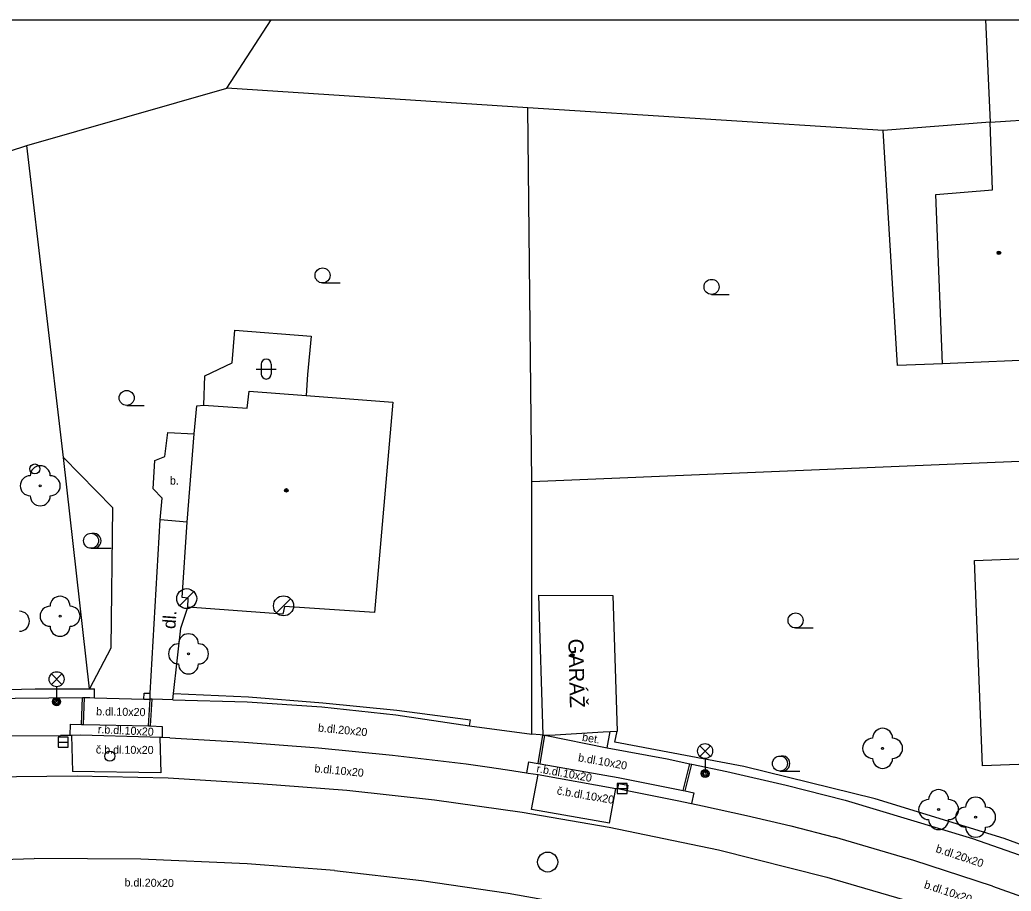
# Model space of a CAD drawing. Extents: x -600309 to -598967, y -1161267 to -1160292.
# Drawn here: x -599777.27 to -599727.72, y -1160335.89 to -1160292.35 of the extents above; entities that cross this region are included whole.
import ezdxf

# ---------------------------------------------------------------- set-up
doc = ezdxf.new("R2010")
doc.units = 0
for name, color, linetype in [('Level 10', 7, 'Continuous'), ('Level 11', 7, 'Continuous'), ('Level 21', 7, 'Continuous'), ('Level 22', 7, 'Continuous'), ('Level 27', 7, 'Continuous'), ('Level 28', 7, 'Continuous'), ('Level 33', 7, 'Continuous'), ('Level 36', 7, 'Continuous'), ('Level 39', 7, 'Continuous'), ('Level 40', 7, 'Continuous'), ('Level 41', 7, 'Continuous'), ('Level 5', 7, 'Continuous'), ('Level 51', 7, 'Continuous'), ('Level 6', 7, 'Continuous'), ('Level 7', 7, 'Continuous'), ('Level 8', 7, 'Continuous'), ('Vrstva 63', 7, 'Continuous')]:
    doc.layers.add(name, color=color, linetype=linetype)

msp = doc.modelspace()

# ---------------------------------------------------------------- linework, layer by layer
at = {"layer": 'Level 10'}
for points in [[(-599783.14, -1160328.38), (-599780.51, -1160328.22), (-599777.87, -1160328.13), (-599775.23, -1160328.11)], [(-599769.77, -1160328.23), (-599770.16, -1160328.21), (-599770.28, -1160328.21), (-599770.75, -1160328.19), (-599774.23, -1160328.1), (-599774.68, -1160328.11), (-599774.77, -1160328.11), (-599775.23, -1160328.11)], [(-599769.77, -1160328.23), (-599766.06, -1160328.44), (-599762.35, -1160328.72), (-599758.65, -1160329.09)], [(-599758.65, -1160329.09), (-599754.96, -1160329.53)], [(-599754.96, -1160329.53), (-599753.92, -1160329.67)], [(-599753.92, -1160329.67), (-599752.89, -1160329.82)], [(-599752.89, -1160329.82), (-599751.95, -1160329.98), (-599751.86, -1160329.99)], [(-599751.86, -1160329.99), (-599751.37, -1160330.06), (-599747.48, -1160330.75), (-599747.39, -1160330.76)], [(-599747.39, -1160330.76), (-599746.92, -1160330.85)], [(-599746.92, -1160330.85), (-599745.66, -1160331.1), (-599744.41, -1160331.35), (-599743.7, -1160331.5), (-599743.16, -1160331.62)], [(-599743.16, -1160331.62), (-599740.95, -1160332.1), (-599738.74, -1160332.62), (-599736.55, -1160333.19)], [(-599732.59, -1160334.36), (-599736.55, -1160333.19)], [(-599787.22, -1160334.78), (-599781.9, -1160334.42), (-599776.56, -1160334.26)], [(-599771.23, -1160334.29), (-599776.56, -1160334.26)], [(-599765.9, -1160334.52), (-599771.23, -1160334.29)], [(-599761.54, -1160334.86), (-599765.9, -1160334.52)], [(-599728.66, -1160335.64), (-599732.59, -1160334.36)], [(-599761.54, -1160334.86), (-599757.2, -1160335.35), (-599752.87, -1160335.98), (-599748.57, -1160336.75)], [(-599728.66, -1160335.64), (-599724.77, -1160337.02), (-599720.92, -1160338.51)]]:
    msp.add_lwpolyline(points, dxfattribs=at)
at = {"layer": 'Level 11'}
msp.add_line((-599729.0024, -1160292.3474), (-599728.77, -1160297.46), dxfattribs=at)
for points in [[(-599768.9099, -1160317.45), (-599770.26, -1160317.33), (-599770.1599, -1160316.25), (-599770.61, -1160315.79), (-599770.52, -1160314.37), (-599770.02, -1160314.17), (-599769.87, -1160312.96), (-599768.56, -1160313.04)], [(-599770.75, -1160326), (-599770.26, -1160317.33)], [(-599769.22, -1160322.75), (-599768.87, -1160321.69)], [(-599769.59, -1160326.01), (-599769.22, -1160322.75)], [(-599774.18, -1160327.56), (-599774.13, -1160326.21)], [(-599774.08, -1160327.56), (-599774.03, -1160326.21)], [(-599770.84, -1160327.63), (-599770.76, -1160326.3)], [(-599770.74, -1160327.63), (-599770.66, -1160326.3)], [(-599774.76, -1160327.55), (-599774.77, -1160328.11)], [(-599774.76, -1160327.55), (-599774.18, -1160327.56), (-599774.08, -1160327.56), (-599770.84, -1160327.63), (-599770.74, -1160327.63), (-599770.15, -1160327.66)], [(-599770.15, -1160327.66), (-599770.16, -1160328.21)], [(-599774.68, -1160328.11), (-599774.63, -1160329.91)], [(-599770.28, -1160328.21), (-599770.23, -1160329.98)], [(-599751.37, -1160329.51), (-599751.13, -1160328.09)], [(-599751.27, -1160329.53), (-599751.03, -1160328.09)], [(-599751.03, -1160328.09), (-599747.92, -1160328.73)], [(-599751.85, -1160329.43), (-599751.95, -1160329.98)], [(-599751.85, -1160329.43), (-599751.37, -1160329.51), (-599751.27, -1160329.53), (-599747.36, -1160330.21), (-599744.12, -1160330.86), (-599744.02, -1160330.88), (-599743.58, -1160330.98)], [(-599744.12, -1160330.86), (-599743.78, -1160329.52)], [(-599744.02, -1160330.88), (-599743.68, -1160329.54)], [(-599783.51, -1160330.39), (-599778.97, -1160330.17), (-599774.41, -1160330.12), (-599769.86, -1160330.23), (-599765.32, -1160330.5)], [(-599770.23, -1160329.98), (-599774.63, -1160329.91)], [(-599751.69, -1160331.81), (-599751.37, -1160330.06)], [(-599765.32, -1160330.5), (-599760.92, -1160330.84), (-599756.54, -1160331.32), (-599752.17, -1160331.94), (-599747.82, -1160332.69)], [(-599747.39, -1160330.76), (-599747.34, -1160330.51), (-599746.88, -1160330.59), (-599746.92, -1160330.85)], [(-599747.8, -1160332.49), (-599747.48, -1160330.75)], [(-599743.58, -1160330.98), (-599743.7, -1160331.5)], [(-599747.8, -1160332.49), (-599751.69, -1160331.81)], [(-599747.82, -1160332.69), (-599742.35, -1160333.82), (-599736.93, -1160335.18), (-599731.57, -1160336.76), (-599726.28, -1160338.56)]]:
    msp.add_lwpolyline(points, dxfattribs=at)
at = {"layer": 'Level 21'}
for points in [[(-599775.09, -1160314.21), (-599772.64, -1160316.72)], [(-599772.64, -1160316.72), (-599772.72, -1160323.74)], [(-599772.72, -1160323.74), (-599773.78, -1160325.77)]]:
    msp.add_lwpolyline(points, dxfattribs=at)
at = {"layer": 'Level 22'}
for centre in [(-599776.25, -1160315.63), (-599775.26, -1160322.15), (-599768.84, -1160324.03), (-599734.15, -1160328.75), (-599731.35, -1160331.81), (-599729.5, -1160332.19)]:
    msp.add_circle(centre, 0.05, dxfattribs=at)
for centre, start, end in [((-599776.25, -1160315.13), 0, 180), ((-599776.75, -1160315.63), 90, 270), ((-599775.75, -1160315.63), 270, 90), ((-599776.25, -1160316.13), 180, 0), ((-599775.26, -1160321.65), 0, 180), ((-599775.76, -1160322.15), 90, 270), ((-599774.76, -1160322.15), 270, 90), ((-599777.29, -1160322.4), 270, 90), ((-599775.26, -1160322.65), 180, 0), ((-599768.84, -1160323.53), 0, 180), ((-599769.34, -1160324.03), 90, 270), ((-599768.34, -1160324.03), 270, 90), ((-599768.84, -1160324.53), 180, 0), ((-599734.15, -1160328.25), 0, 180), ((-599734.65, -1160328.75), 90, 270), ((-599733.65, -1160328.75), 270, 90), ((-599734.15, -1160329.25), 180, 0), ((-599731.35, -1160331.31), 0, 180), ((-599729.5, -1160331.69), 0, 180), ((-599731.85, -1160331.81), 90, 270), ((-599730.85, -1160331.81), 270, 90), ((-599730, -1160332.19), 90, 270), ((-599729, -1160332.19), 270, 90), ((-599731.35, -1160332.31), 180, 0), ((-599729.5, -1160332.69), 180, 0)]:
    msp.add_arc(centre, 0.5, start, end, dxfattribs=at)
at = {"layer": 'Level 27'}
for p, q in [((-599769.284, -1160321.623), (-599768.577, -1160320.916)), ((-599764.444, -1160321.983), (-599763.737, -1160321.276)), ((-599775.36, -1160328.44), (-599774.86, -1160328.44)), ((-599747.41, -1160330.76), (-599746.91, -1160330.76))]:
    msp.add_line(p, q, dxfattribs=at)
for points in [[(-599775.36, -1160328.69), (-599774.86, -1160328.69), (-599774.86, -1160328.19), (-599775.36, -1160328.19)], [(-599747.41, -1160331.01), (-599746.91, -1160331.01), (-599746.91, -1160330.51), (-599747.41, -1160330.51)]]:
    msp.add_lwpolyline(points, close=True, dxfattribs=at)
for centre in [(-599768.93, -1160321.27), (-599764.09, -1160321.63), (-599750.89, -1160334.43)]:
    msp.add_circle(centre, 0.5, dxfattribs=at)
at = {"layer": 'Level 28'}
for centre in [(-599776.52, -1160314.79), (-599772.77, -1160329.14)]:
    msp.add_circle(centre, 0.25, dxfattribs=at)
at = {"layer": 'Level 33'}
for p, q in [((-599775.695, -1160325.56), (-599775.165, -1160325.03)), ((-599775.695, -1160325.03), (-599775.165, -1160325.56)), ((-599775.43, -1160325.67), (-599775.43, -1160326.42)), ((-599743.285, -1160329.15), (-599742.755, -1160328.62)), ((-599743.285, -1160328.62), (-599742.755, -1160329.15)), ((-599743.02, -1160329.26), (-599743.02, -1160330.01))]:
    msp.add_line(p, q, dxfattribs=at)
for centre, radius in [((-599775.43, -1160325.295), 0.375), ((-599775.43, -1160326.42), 0.2), ((-599775.43, -1160326.42), 0.1445), ((-599775.43, -1160326.42), 0.0876), ((-599743.02, -1160328.885), 0.375), ((-599743.02, -1160330.01), 0.2), ((-599743.02, -1160330.01), 0.1445), ((-599743.02, -1160330.01), 0.0876)]:
    msp.add_circle(centre, radius, dxfattribs=at)
at = {"layer": 'Level 36'}
for p, q in [((-599762.14, -1160305.495), (-599761.265, -1160305.495)), ((-599742.7, -1160306.065), (-599741.825, -1160306.065)), ((-599765.456, -1160309.796), (-599764.456, -1160309.796)), ((-599765.206, -1160309.546), (-599765.206, -1160310.046)), ((-599764.706, -1160309.546), (-599764.706, -1160310.046)), ((-599771.93, -1160311.615), (-599771.055, -1160311.615)), ((-599773.71, -1160318.755), (-599772.71, -1160318.755)), ((-599738.5, -1160322.735), (-599737.625, -1160322.735)), ((-599739.28, -1160329.885), (-599738.28, -1160329.885))]:
    msp.add_line(p, q, dxfattribs=at)
for centre in [(-599762.1401, -1160305.1199), (-599742.7001, -1160305.6899), (-599771.9301, -1160311.2399), (-599773.71, -1160318.3796), (-599738.5001, -1160322.3599), (-599739.28, -1160329.5096)]:
    msp.add_circle(centre, 0.375, dxfattribs=at)
for centre, radius, start, end in [((-599764.9557, -1160309.5463), 0.25, 0, 180), ((-599764.9557, -1160310.0463), 0.25, 180, 0), ((-599773.585, -1160318.3796), 0.375, 260.40593, 99.59407), ((-599739.155, -1160329.5096), 0.375, 260.40593, 99.59407)]:
    msp.add_arc(centre, radius, start, end, dxfattribs=at)
at = {"layer": 'Level 39'}
for centre, radius in [((-599728.34, -1160303.99), 0.09), ((-599728.34, -1160303.99), 0.0398), ((-599763.95, -1160315.86), 0.09), ((-599763.95, -1160315.86), 0.0398), ((-599749.6599, -1160324.1), 0.09), ((-599749.6599, -1160324.1), 0.0398)]:
    msp.add_circle(centre, radius, dxfattribs=at)
at = {"layer": 'Level 5'}
for points in [[(-599728.77, -1160297.46), (-599726.2199, -1160297.29)], [(-599728.65, -1160300.84), (-599728.77, -1160297.46)], [(-599731.49, -1160301.08), (-599728.65, -1160300.84)], [(-599731.15, -1160309.54), (-599731.49, -1160301.08)], [(-599725.74, -1160309.31), (-599731.15, -1160309.54)], [(-599765.9, -1160311.75), (-599765.81, -1160310.9099)], [(-599765.81, -1160310.9099), (-599762.96, -1160311.12)], [(-599762.96, -1160311.12), (-599758.62, -1160311.46)], [(-599768.56, -1160313.04), (-599768.42, -1160311.63)], [(-599768.42, -1160311.63), (-599768.08, -1160311.61)], [(-599768.08, -1160311.61), (-599765.9, -1160311.75)], [(-599758.62, -1160311.46), (-599759.54, -1160321.96)], [(-599768.9099, -1160317.45), (-599768.56, -1160313.04)], [(-599769.1599, -1160321.21), (-599768.9099, -1160317.45)], [(-599729.55, -1160319.37), (-599713.51, -1160318.74)], [(-599729.1599, -1160329.63), (-599729.55, -1160319.37)], [(-599768.86, -1160321.25), (-599769.1599, -1160321.21)], [(-599768.87, -1160321.69), (-599768.86, -1160321.25)], [(-599751.35, -1160321.1), (-599751.13, -1160328.09)], [(-599751.35, -1160321.1), (-599747.63, -1160321.11)], [(-599747.63, -1160321.11), (-599747.41, -1160327.89)], [(-599764.12, -1160322.04), (-599768.87, -1160321.69)], [(-599764.04, -1160321.67), (-599764.12, -1160322.04)], [(-599759.54, -1160321.96), (-599764.04, -1160321.67)], [(-599751.13, -1160328.09), (-599751.03, -1160328.09), (-599750.52, -1160328.07)], [(-599748.12, -1160327.93), (-599747.76, -1160327.91), (-599747.41, -1160327.89)], [(-599722.82, -1160329.39), (-599729.1599, -1160329.63)]]:
    msp.add_lwpolyline(points, dxfattribs=at)
at = {"layer": 'Level 51'}
msp.add_line((-599766.93, -1160295.77), (-599764.7013, -1160292.3474), dxfattribs=at)
for points in [[(-599776.92, -1160298.63), (-599766.93, -1160295.77)], [(-599751.88, -1160296.74), (-599766.93, -1160295.77)], [(-599734.13, -1160297.88), (-599751.88, -1160296.74)], [(-599751.68, -1160315.43), (-599751.88, -1160296.74)], [(-599728.77, -1160297.46), (-599734.13, -1160297.88)], [(-599733.4, -1160309.62), (-599734.13, -1160297.88)], [(-599789.02, -1160302.58), (-599776.92, -1160298.63)], [(-599766.65, -1160309.49), (-599766.52, -1160307.86)], [(-599766.52, -1160307.86), (-599762.71, -1160308.1599)], [(-599762.71, -1160308.1599), (-599762.89, -1160310.07)], [(-599768.03, -1160310.13), (-599766.65, -1160309.49)], [(-599731.15, -1160309.54), (-599733.4, -1160309.62)], [(-599768.08, -1160311.61), (-599768.03, -1160310.13)], [(-599762.89, -1160310.07), (-599762.96, -1160311.12)], [(-599729.73, -1160314.52), (-599751.68, -1160315.43)]]:
    msp.add_lwpolyline(points, dxfattribs=at)
at = {"layer": 'Level 6'}
msp.add_lwpolyline([(-599750.52, -1160328.07), (-599748.12, -1160327.93)], dxfattribs=at)
at = {"layer": 'Level 7'}
for points in [[(-599773.78, -1160325.77), (-599775.09, -1160314.21), (-599776.92, -1160298.63)], [(-599714.44, -1160313.89), (-599729.73, -1160314.52)], [(-599751.68, -1160328.04), (-599751.68, -1160315.43)], [(-599784.71, -1160326.2), (-599781.98, -1160325.99), (-599779.25, -1160325.85), (-599776.51, -1160325.78)], [(-599784.7, -1160326.64), (-599784.34, -1160326.62), (-599784.24, -1160326.61), (-599779.21, -1160326.26), (-599774.13, -1160326.21), (-599774.03, -1160326.21), (-599773.77, -1160326.21)], [(-599776.51, -1160325.78), (-599773.78, -1160325.77), (-599773.54, -1160325.77)], [(-599773.77, -1160326.21), (-599773.54, -1160326.23)], [(-599773.54, -1160326.23), (-599773.54, -1160325.77)], [(-599771.08, -1160326.29), (-599771.06, -1160326)], [(-599771.06, -1160326), (-599770.75, -1160326)], [(-599770.76, -1160326.3), (-599770.75, -1160326)], [(-599769.62, -1160326.32), (-599769.59, -1160326.01)], [(-599769.59, -1160326.01), (-599765.84, -1160326.18), (-599762.13, -1160326.47), (-599758.43, -1160326.85), (-599754.75, -1160327.32)], [(-599771.08, -1160326.29), (-599770.76, -1160326.3)], [(-599769.62, -1160326.32), (-599765.9, -1160326.43), (-599762.18, -1160326.68), (-599758.48, -1160327.08), (-599754.8, -1160327.62)], [(-599754.8, -1160327.62), (-599754.75, -1160327.32)], [(-599751.13, -1160328.09), (-599751.26, -1160328.08), (-599751.68, -1160328.04)], [(-599747.92, -1160328.73), (-599747.76, -1160327.91)], [(-599747.53, -1160328.44), (-599747.41, -1160327.89)], [(-599721.74, -1160335.59), (-599728.07, -1160333.26), (-599734.52, -1160331.28), (-599741.08, -1160329.6599), (-599747.53, -1160328.44)], [(-599747.92, -1160328.73), (-599744.92, -1160329.28), (-599743.78, -1160329.52), (-599743.68, -1160329.54), (-599741.94, -1160329.9), (-599738.97, -1160330.59), (-599736.02, -1160331.34)], [(-599736.02, -1160331.34), (-599729.65, -1160333.26), (-599723.38, -1160335.46)]]:
    msp.add_lwpolyline(points, dxfattribs=at)
at = {"layer": 'Level 8'}
for points in [[(-599773.54, -1160326.23), (-599771.08, -1160326.29)], [(-599769.62, -1160326.32), (-599770.66, -1160326.3), (-599770.76, -1160326.3)], [(-599754.8, -1160327.62), (-599751.68, -1160328.04)]]:
    msp.add_lwpolyline(points, dxfattribs=at)
at = {"layer": 'Vrstva 63'}
msp.add_lwpolyline([(-600308.541, -1160292.3474), (-598967.1085, -1160292.3474), (-598967.1085, -1161267.0314), (-600308.541, -1161267.0314)], close=True, dxfattribs=at)

# ---------------------------------------------------------------- texts
at = {"layer": 'Level 40'}
msp.add_text('b.', height=0.4, dxfattribs=at).set_placement((-599769.77, -1160315.57))
for s, height, rotation, p in [('dl.', 0.65, 85.76601, (-599769.5, -1160322.8)), ('b.dl.10x20', 0.4, 359, (-599773.46, -1160327.1)), ('r.b.dl.10x20', 0.399972, 357.18969, (-599773.38, -1160327.99)), ('b.dl.20x20', 0.39997, 354.52596, (-599762.38, -1160327.91)), ('bet.', 0.4, 350.48552, (-599749.19, -1160328.37)), ('č.b.dl.10x20', 0.400002, 359.55381, (-599773.47, -1160329.01)), ('b.dl.10x20', 0.4, 349.96959, (-599749.39, -1160329.39)), ('b.dl.10x20', 0.4, 354.52596, (-599762.56, -1160329.94)), ('r.b.dl.10x20', 0.39996, 349.85554, (-599751.47, -1160329.94)), ('č.b.dl.10x20', 0.400002, 350.48552, (-599750.45, -1160331.05)), ('b.dl.20x20', 0.39998, 341.7497, (-599731.53, -1160333.93)), ('b.dl.20x20', 0.39997, 359.31721, (-599772.04, -1160335.65)), ('b.dl.10x20', 0.4, 341.7497, (-599732.11, -1160335.72))]:
    msp.add_text(s, height=height, rotation=rotation, dxfattribs=at).set_placement(p)
at = {"layer": 'Level 41'}
msp.add_text('GARÁŽ', height=0.75, rotation=271.38526, dxfattribs=at).set_placement((-599749.86, -1160323.28))

doc.saveas('drawing.dxf')
